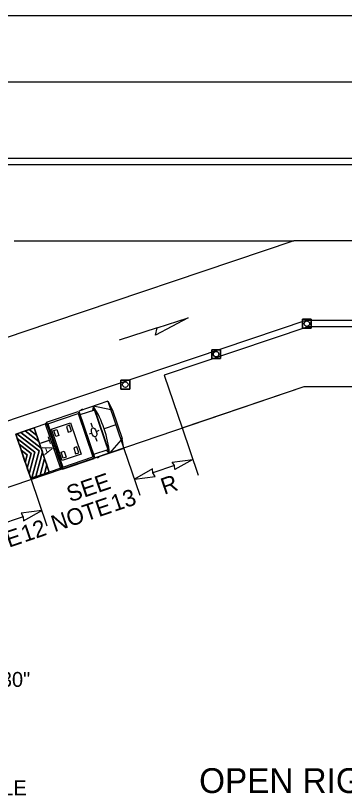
# Model space of a CAD drawing. Extents: x 99999.1 to 100055.7, y 99995 to 100013.2.
# Drawn here: x 100030.318 to 100031.905, y 100004.789 to 100008.556 of the extents above; entities that cross this region are included whole.
import ezdxf

# ---------------------------------------------------------------- set-up
doc = ezdxf.new("R2010")
doc.units = 0
for name, color, linetype in [('RD_MK_LineDblYellowCenter', 7, 'Continuous'), ('RD_MK_LineEdgeWhite', 7, 'Continuous'), ('RD_MK_LineEdgeYellow', 7, 'Continuous'), ('RD_MK_LineLane', 7, 'Continuous'), ('SH_DE_DetailHeading2Text', 7, 'Continuous'), ('TR_SN_ConstructionSigns', 7, 'Continuous'), ('TR_WZ_TrafficCone', 7, 'Continuous'), ('TR_WZ_TransportableAttenuator', 7, 'Continuous'), ('TR_WZ_WorkZoneDetails', 7, 'Continuous'), ('TR_WZ_WorkZoneTextCurrent', 7, 'Continuous')]:
    doc.layers.add(name, color=color, linetype=linetype)

msp = doc.modelspace()

# ---------------------------------------------------------------- linework, layer by layer
at = {"layer": 'RD_MK_LineDblYellowCenter'}
for p, q in [((100028.2115, 100007.868), (100035.4465, 100007.868)), ((100028.1785, 100007.836), (100035.4135, 100007.836))]:
    msp.add_line(p, q, dxfattribs=at)
at = {"layer": 'RD_MK_LineEdgeWhite'}
msp.add_line((100028.195, 100008.236), (100035.43, 100008.236), dxfattribs=at)
at = {"layer": 'RD_MK_LineEdgeYellow'}
for p, q in [((100031.723, 100007.084), (100028.095, 100005.8589)), ((100031.7238, 100007.084), (100033.2341, 100007.084)), ((100030.3526, 100007.0266), (100028.095, 100006.2642))]:
    msp.add_line(p, q, dxfattribs=at)
at = {"layer": 'RD_MK_LineLane'}
msp.add_lwpolyline([(100033.2341, 100007.468), (100031.6607, 100007.468)], dxfattribs=at)
at = {"layer": 'TR_WZ_TrafficCone'}
for points in [[(100031.7025, 100007.0893), (100031.7451, 100007.0893), (100031.7451, 100007.0466), (100031.7025, 100007.0466), (100031.7025, 100007.0893)], [(100031.7025, 100007.0466), (100031.7451, 100007.0466), (100031.7451, 100007.0893), (100031.7025, 100007.0893), (100031.7025, 100007.0466)], [(100031.2645, 100006.9418), (100031.3071, 100006.9418), (100031.3071, 100006.8992), (100031.2645, 100006.8992), (100031.2645, 100006.9418)], [(100031.2645, 100006.8992), (100031.3071, 100006.8992), (100031.3071, 100006.9418), (100031.2645, 100006.9418), (100031.2645, 100006.8992)], [(100030.8265, 100006.7944), (100030.8691, 100006.7944), (100030.8691, 100006.7518), (100030.8265, 100006.7518), (100030.8265, 100006.7944)], [(100030.8265, 100006.7518), (100030.8691, 100006.7518), (100030.8691, 100006.7944), (100030.8265, 100006.7944), (100030.8265, 100006.7518)]]:
    msp.add_lwpolyline(points, dxfattribs=at)
for centre in [(100031.7238, 100007.0679), (100031.2858, 100006.9205), (100030.8478, 100006.7731)]:
    msp.add_circle(centre, 0.0133, dxfattribs=at)
at = {"layer": 'TR_WZ_TransportableAttenuator'}
for p, q in [((100030.7641, 100006.6926), (100030.6228, 100006.6446)), ((100030.7641, 100006.6926), (100030.8413, 100006.4654)), ((100030.7641, 100006.6926), (100030.7866, 100006.6492)), ((100030.6982, 100006.6506), (100030.6288, 100006.627)), ((100030.641, 100006.6544), (100030.6325, 100006.6515)), ((100030.6922, 100006.6682), (100030.6892, 100006.6475)), ((100030.6922, 100006.6682), (100030.7694, 100006.441)), ((100030.6934, 100006.6686), (100030.7707, 100006.4414)), ((100030.7782, 100006.651), (100030.6934, 100006.6686)), ((100030.7866, 100006.6492), (100030.8327, 100006.5137)), ((100030.4669, 100006.5916), (100030.6207, 100006.6439)), ((100030.4743, 100006.5841), (100030.6195, 100006.6334)), ((100030.6195, 100006.6334), (100030.6905, 100006.4243)), ((100030.6207, 100006.6439), (100030.698, 100006.4167)), ((100030.6228, 100006.6446), (100030.7001, 100006.4174)), ((100030.4691, 100006.5849), (100030.4082, 100006.5642)), ((100030.4633, 100006.5785), (100030.5333, 100006.3726)), ((100030.4643, 100006.5866), (100030.4676, 100006.5877)), ((100030.4669, 100006.5916), (100030.5441, 100006.3644)), ((100030.4676, 100006.5877), (100030.5423, 100006.3679)), ((100030.4693, 100006.5845), (100030.5417, 100006.3716)), ((100030.4743, 100006.5841), (100030.5454, 100006.3749)), ((100030.6816, 100006.5881), (100030.6878, 100006.5697)), ((100030.8027, 100006.5791), (100030.7459, 100006.5598)), ((100030.3247, 100006.5358), (100030.344, 100006.5424)), ((100030.344, 100006.5424), (100030.3247, 100006.5358)), ((100030.4319, 100006.4532), (100030.3247, 100006.5358)), ((100030.3247, 100006.5358), (100030.4319, 100006.4532)), ((100030.344, 100006.5424), (100030.4412, 100006.4669)), ((100030.4412, 100006.4669), (100030.344, 100006.5424)), ((100030.365, 100006.5495), (100030.3843, 100006.556)), ((100030.3843, 100006.556), (100030.365, 100006.5495)), ((100030.4306, 100006.4983), (100030.365, 100006.5495)), ((100030.365, 100006.5495), (100030.4306, 100006.4983)), ((100030.3843, 100006.556), (100030.4205, 100006.528)), ((100030.4205, 100006.528), (100030.3843, 100006.556)), ((100030.4807, 100006.3509), (100030.4082, 100006.5642)), ((100030.6743, 100006.5356), (100030.6837, 100006.5387)), ((100030.6865, 100006.5391), (100030.6865, 100006.5391)), ((100030.7194, 100006.5509), (100030.71, 100006.5476)), ((100030.3258, 100006.5135), (100030.4118, 100006.4471)), ((100030.3351, 100006.4859), (100030.3258, 100006.5135)), ((100030.4118, 100006.4471), (100030.3258, 100006.5135)), ((100030.3258, 100006.5135), (100030.3351, 100006.4859)), ((100030.4205, 100006.528), (100030.4306, 100006.4983)), ((100030.4306, 100006.4983), (100030.4205, 100006.528)), ((100030.7122, 100006.498), (100030.7059, 100006.5164)), ((100030.8272, 100006.507), (100030.7707, 100006.4414)), ((100030.8413, 100006.4654), (100030.8327, 100006.5137)), ((100030.3934, 100006.4412), (100030.3351, 100006.4859)), ((100030.3351, 100006.4859), (100030.3934, 100006.4412)), ((100030.4412, 100006.4669), (100030.4477, 100006.4479)), ((100030.4477, 100006.4479), (100030.4412, 100006.4669)), ((100030.4928, 100006.4915), (100030.501, 100006.4896)), ((100030.5001, 100006.4762), (100030.5032, 100006.4772)), ((100030.5005, 100006.4799), (100030.5027, 100006.4735)), ((100030.5037, 100006.4595), (100030.509, 100006.4661)), ((100030.7634, 100006.4586), (100030.6941, 100006.435)), ((100030.8413, 100006.4654), (100030.7001, 100006.4174)), ((100030.3451, 100006.4566), (100030.3748, 100006.434)), ((100030.3652, 100006.3975), (100030.3451, 100006.4566)), ((100030.3748, 100006.434), (100030.3451, 100006.4566)), ((100030.3451, 100006.4566), (100030.3652, 100006.3975)), ((100030.3748, 100006.434), (100030.3652, 100006.3975)), ((100030.3652, 100006.3975), (100030.3748, 100006.434)), ((100030.3746, 100006.3699), (100030.3934, 100006.4412)), ((100030.3934, 100006.4412), (100030.3746, 100006.3699)), ((100030.4118, 100006.4471), (100030.384, 100006.342)), ((100030.384, 100006.342), (100030.4118, 100006.4471)), ((100030.3972, 100006.3223), (100030.4319, 100006.4532)), ((100030.4319, 100006.4532), (100030.3972, 100006.3223)), ((100030.4477, 100006.4479), (100030.4162, 100006.3288)), ((100030.4162, 100006.3288), (100030.4477, 100006.4479)), ((100030.5454, 100006.3749), (100030.6905, 100006.4243)), ((100030.7204, 100006.4208), (100030.7119, 100006.4179)), ((100030.756, 100006.456), (100030.7694, 100006.441)), ((100030.4371, 100006.3359), (100030.4584, 100006.4165)), ((100030.4584, 100006.4165), (100030.4371, 100006.3359)), ((100030.4691, 100006.3851), (100030.4575, 100006.3428)), ((100030.4575, 100006.3428), (100030.4691, 100006.3851)), ((100030.4584, 100006.4165), (100030.4691, 100006.3851)), ((100030.4691, 100006.3851), (100030.4584, 100006.4165)), ((100030.5441, 100006.3644), (100030.698, 100006.4167)), ((100030.384, 100006.342), (100030.3746, 100006.3699)), ((100030.3746, 100006.3699), (100030.384, 100006.342)), ((100030.5417, 100006.3716), (100030.4807, 100006.3509)), ((100030.539, 100006.3668), (100030.5423, 100006.3679)), ((100030.4162, 100006.3288), (100030.3972, 100006.3223)), ((100030.3972, 100006.3223), (100030.4162, 100006.3288)), ((100030.4575, 100006.3428), (100030.4371, 100006.3359)), ((100030.4371, 100006.3359), (100030.4575, 100006.3428))]:
    msp.add_line(p, q, dxfattribs=at)
for points in [[(100030.4917, 100006.5578), (100030.5826, 100006.5887), (100030.6341, 100006.4372), (100030.5432, 100006.4063)], [(100030.5782, 100006.5767), (100030.5631, 100006.5715), (100030.5727, 100006.5431), (100030.5879, 100006.5483)], [(100030.4807, 100006.3507), (100030.3914, 100006.3203), (100030.3188, 100006.5338), (100030.4082, 100006.5642)], [(100030.5025, 100006.5509), (100030.5176, 100006.5561), (100030.5273, 100006.5277), (100030.5121, 100006.5225)], [(100030.6136, 100006.4725), (100030.5985, 100006.4674), (100030.6081, 100006.439), (100030.6233, 100006.4441)], [(100030.5379, 100006.4468), (100030.553, 100006.4519), (100030.5627, 100006.4235), (100030.5475, 100006.4184)]]:
    msp.add_lwpolyline(points, close=True, dxfattribs=at)
msp.add_lwpolyline([(100030.4082, 100006.5642), (100030.3188, 100006.5338), (100030.3914, 100006.3203), (100030.4807, 100006.3509)], dxfattribs=at)
for centre, major_axis, start_param, end_param in [((100030.6311, 100006.5207), (-0.0811, 0.2385), 4.215852, 5.209111), ((100030.4666, 100006.5796), (-0.00236, 0.00693), 6.283185, 7.853982), ((100030.5366, 100006.3737), (0.00236, -0.00693), 4.712389, 6.283185)]:
    msp.add_ellipse(centre, major_axis=major_axis, ratio=0.481608, start_param=start_param, end_param=end_param, dxfattribs=at)
for centre, major_axis in [((100030.6969, 100006.5431), (0.0074, -0.0219)), ((100030.5016, 100006.4767), (0.00109, -0.0032))]:
    msp.add_ellipse(centre, major_axis=major_axis, ratio=0.481608, dxfattribs=at)
at = {"layer": 'TR_WZ_WorkZoneDetails'}
for p, q in [((100028.195, 100008.556), (100035.43, 100008.556)), ((100030.3116, 100007.468), (100031.6607, 100007.468)), ((100031.6607, 100007.468), (100030.3526, 100007.0263)), ((100031.0007, 100007.0479), (100030.8173, 100006.9881)), ((100028.095, 100005.5349), (100031.7105, 100006.764)), ((100031.7105, 100006.764), (100033.2341, 100006.764)), ((100031.1223, 100006.564), (100031.2, 100006.3354)), ((100030.8413, 100006.4654), (100030.9181, 100006.2395)), ((100031.085, 100006.3823), (100030.9807, 100006.3468)), ((100030.3914, 100006.3203), (100030.4694, 100006.0909)), ((100030.3553, 100006.1353), (100029.8955, 100005.979))]:
    msp.add_line(p, q, dxfattribs=at)
for points in [[(100033.7873, 100007.436), (100033.2263, 100007.052), (100031.7283, 100007.052), (100031.0359, 100006.8182), (100031.0359, 100006.8182), (100031.0359, 100006.8182), (100031.1223, 100006.564), (100031.1223, 100006.564), (100031.1223, 100006.564), (100031.7105, 100006.764), (100033.2341, 100006.764), (100033.5146, 100006.956), (100033.7951, 100007.148), (100035.35, 100007.148), (100035.35, 100007.436)], [(100031.1502, 100007.0966), (100030.9933, 100007.013), (100031.0007, 100007.0479)], [(100031.1738, 100006.4124), (100031.0869, 100006.3626), (100031.085, 100006.3823), (100031.0745, 100006.3991)], [(100030.8919, 100006.3166), (100030.9912, 100006.33), (100030.9807, 100006.3468), (100030.9788, 100006.3665)], [(100030.4441, 100006.1655), (100030.3448, 100006.1521), (100030.3553, 100006.1353), (100030.3572, 100006.1156)]]:
    msp.add_lwpolyline(points, close=True, dxfattribs=at)

# ---------------------------------------------------------------- texts
at = {"layer": 'SH_DE_DetailHeading2Text'}
msp.add_text('OPEN RIGHT ON-RAMP DETAIL', height=0.12, rotation=360, dxfattribs=at).set_placement((100031.2039, 100004.8003))
at = {"layer": 'TR_SN_ConstructionSigns'}
for s, p in [('30"', (100030.2473, 100005.3132)), ('BIKE-VEHICLE', (100029.7086, 100004.79))]:
    msp.add_text(s, height=0.072, rotation=360, dxfattribs=at).set_placement(p)
at = {"layer": 'TR_WZ_TransportableAttenuator'}
msp.add_text('TA', height=0.048, rotation=288.775, dxfattribs=at).set_placement((100030.4317, 100006.5085))
at = {"layer": 'TR_WZ_WorkZoneTextCurrent'}
for s, p in [('SEE', (100030.5812, 100006.2042)), ('R', (100031.0353, 100006.2407)), ('13', (100030.7945, 100006.1584)), ('NOTE', (100030.5059, 100006.0603)), ('12', (100030.3609, 100006.0105)), ('NOTE', (100030.0723, 100005.9124))]:
    msp.add_text(s, height=0.08, rotation=18.775, dxfattribs=at).set_placement(p)

doc.saveas('drawing.dxf')
